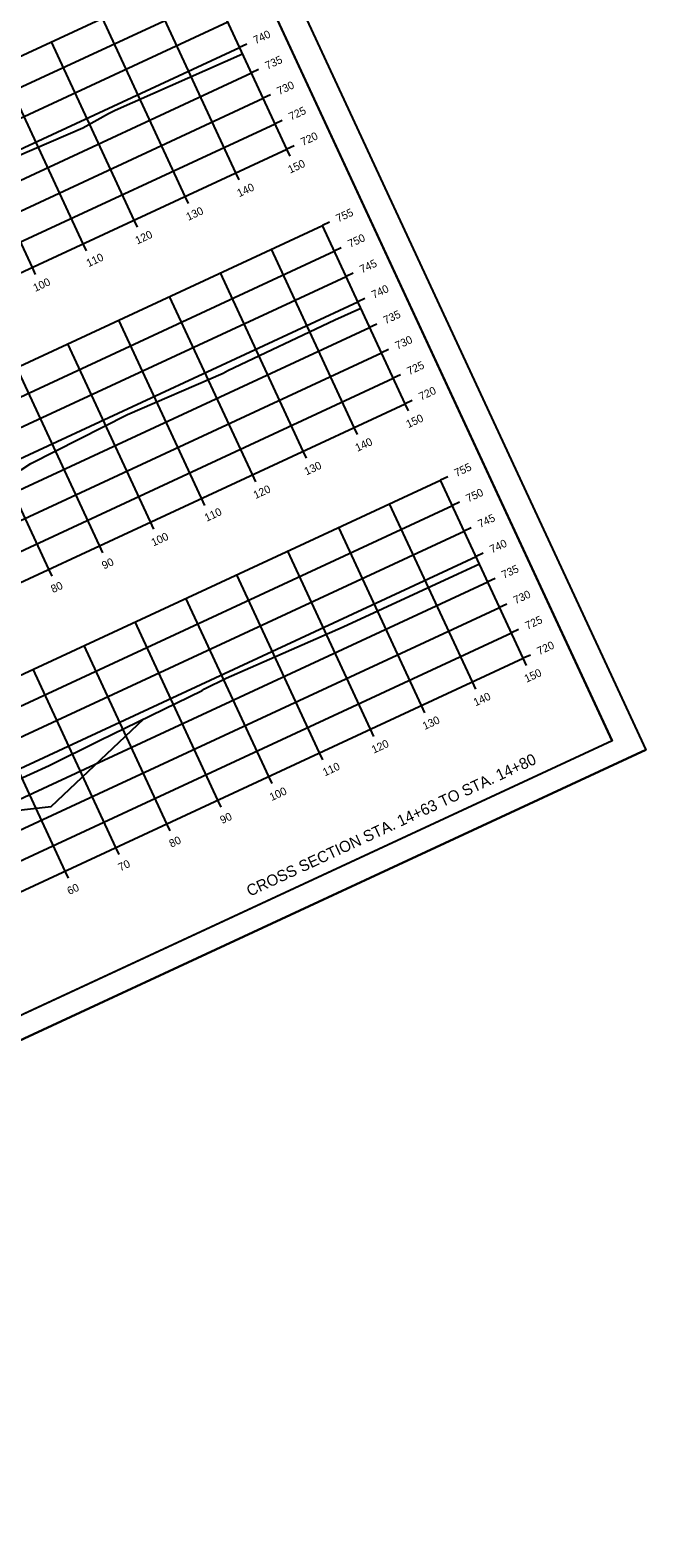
# Model space of a CAD drawing. Extents: x 1354696 to 1366163, y 660729 to 670380.
# Drawn here: x 1359055.3 to 1359165, y 665712.2 to 665980.8 of the extents above; entities that cross this region are included whole.
import ezdxf

# ---------------------------------------------------------------- set-up
doc = ezdxf.new("R2010")
doc.units = 0
for name, color, linetype in [('R_Axis', 7, 'Continuous'), ('R_Axis Annot', 7, 'Continuous'), ('R_Border', 7, 'Continuous'), ('R_Draft', 7, 'Continuous'), ('R_Exist Surface', 7, 'Continuous'), ('R_Fin Surface', 7, 'Continuous'), ('R_Grid', 7, 'Continuous'), ('R_No Plot', 7, 'Continuous')]:
    doc.layers.add(name, color=color, linetype=linetype)

msp = doc.modelspace()

# ---------------------------------------------------------------- linework, layer by layer
at = {"layer": 'R_Axis'}
for p, q in [((1359101.06, 665959.57), (1359086.32, 665991.32)), ((1359093.91, 665978.3), (1359092.64, 665977.71)), ((1359096.02, 665973.77), (1359094.75, 665973.18)), ((1359098.12, 665969.23), (1359096.85, 665968.64)), ((1359100.23, 665964.7), (1359098.96, 665964.11)), ((1358828.96, 665833.24), (1359101.06, 665959.57)), ((1359102.33, 665960.16), (1359101.06, 665959.57)), ((1359101.65, 665958.3), (1359101.06, 665959.57)), ((1359092.58, 665954.09), (1359091.99, 665955.36)), ((1359083.51, 665949.88), (1359082.92, 665951.15)), ((1359074.44, 665945.67), (1359073.85, 665946.94)), ((1359108.65, 665946.56), (1359107.38, 665945.97)), ((1359122.12, 665914.22), (1359107.38, 665945.97)), ((1359065.37, 665941.46), (1359064.78, 665942.73)), ((1359110.75, 665942.02), (1359109.48, 665941.43)), ((1359056.3, 665937.25), (1359055.71, 665938.52)), ((1359112.86, 665937.49), (1359111.59, 665936.9)), ((1359114.97, 665932.95), (1359113.7, 665932.36)), ((1359117.07, 665928.42), (1359115.8, 665927.83)), ((1359119.18, 665923.88), (1359117.91, 665923.29)), ((1359121.28, 665919.35), (1359120.01, 665918.76)), ((1358850.01, 665787.89), (1359122.12, 665914.22)), ((1359123.39, 665914.81), (1359122.12, 665914.22)), ((1359122.71, 665912.95), (1359122.12, 665914.22)), ((1359113.64, 665908.74), (1359113.05, 665910.01)), ((1359104.57, 665904.53), (1359103.98, 665905.8)), ((1359095.5, 665900.32), (1359094.91, 665901.59)), ((1359129.7, 665901.21), (1359128.43, 665900.62)), ((1359143.17, 665868.87), (1359128.43, 665900.62)), ((1359086.43, 665896.11), (1359085.84, 665897.38)), ((1359131.81, 665896.67), (1359130.54, 665896.08)), ((1359077.36, 665891.9), (1359076.77, 665893.17)), ((1359133.91, 665892.14), (1359132.65, 665891.55)), ((1359068.29, 665887.69), (1359067.7, 665888.96)), ((1359136.02, 665887.6), (1359134.75, 665887.01)), ((1359059.22, 665883.48), (1359058.63, 665884.75)), ((1359138.13, 665883.07), (1359136.86, 665882.48)), ((1359140.23, 665878.53), (1359138.96, 665877.94)), ((1359142.34, 665874), (1359141.07, 665873.41)), ((1358871.07, 665742.54), (1359143.17, 665868.87)), ((1359144.44, 665869.46), (1359143.17, 665868.87)), ((1359143.76, 665867.6), (1359143.17, 665868.87)), ((1359134.69, 665863.39), (1359134.1, 665864.66)), ((1359125.62, 665859.18), (1359125.03, 665860.45)), ((1359116.55, 665854.97), (1359115.96, 665856.24)), ((1359107.48, 665850.76), (1359106.89, 665852.03)), ((1359098.41, 665846.55), (1359097.82, 665847.82)), ((1359089.34, 665842.34), (1359088.75, 665843.61)), ((1359080.27, 665838.13), (1359079.68, 665839.4)), ((1359071.2, 665833.91), (1359070.61, 665835.18)), ((1359062.13, 665829.7), (1359061.54, 665830.97))]:
    msp.add_line(p, q, dxfattribs=at)
at = {"layer": 'R_Border'}
for q in [(1359072.49, 666040.53), (1358872.23, 665721.03)]:
    msp.add_line((1359159.01, 665854.18), q, dxfattribs=at)
at = {"layer": 'R_Exist Surface'}
for points in [[(1359052.99, 665958.3), (1359064.71, 665963.37), (1359069.26, 665965.94), (1359070.45, 665966.51), (1359093.17, 665976.58)], [(1359053.71, 665902.42), (1359055.46, 665903.6), (1359072.65, 665912.31), (1359089.69, 665919.67), (1359090.54, 665920.16), (1359109.57, 665929.16), (1359114.23, 665931.22)], [(1359052.19, 665846.79), (1359055.33, 665848.21), (1359058.69, 665849.76), (1359067.68, 665854.26), (1359085.98, 665863.15), (1359086.37, 665863.41), (1359090.21, 665865.35), (1359094.6, 665867.25), (1359111.11, 665874.49), (1359131.53, 665883.93), (1359135.35, 665885.72)]]:
    msp.add_lwpolyline(points, dxfattribs=at)
at = {"layer": 'R_Fin Surface'}
msp.add_lwpolyline([(1358936.65, 665790.65), (1358947.7, 665791.9), (1358971.24, 665814.12), (1358974.3, 665816.16), (1358981.35, 665820.85), (1358986.74, 665823.49), (1358996.62, 665828.32), (1359006.69, 665832.75), (1359012.24, 665835.06), (1359019.88, 665837.33), (1359023.86, 665838.51), (1359059.06, 665842.5), (1359075.59, 665858.1)], dxfattribs=at)
at = {"layer": 'R_Grid'}
for p, q in [((1358814.22, 665864.99), (1359086.32, 665991.32)), ((1359101.06, 665959.57), (1359086.32, 665991.32)), ((1358816.33, 665860.45), (1359088.43, 665986.78)), ((1359091.99, 665955.36), (1359077.25, 665987.11)), ((1358818.43, 665855.92), (1359090.53, 665982.25)), ((1359082.92, 665951.15), (1359068.18, 665982.9)), ((1359073.85, 665946.94), (1359059.11, 665978.69)), ((1358820.54, 665851.38), (1359092.64, 665977.71)), ((1358822.64, 665846.85), (1359094.75, 665973.18)), ((1359064.78, 665942.73), (1359050.04, 665974.48)), ((1359055.71, 665938.52), (1359040.97, 665970.26)), ((1358824.75, 665842.31), (1359096.85, 665968.64)), ((1358826.85, 665837.78), (1359098.96, 665964.11)), ((1358828.96, 665833.24), (1359101.06, 665959.57)), ((1358835.27, 665819.64), (1359107.38, 665945.97)), ((1359122.12, 665914.22), (1359107.38, 665945.97)), ((1358837.38, 665815.1), (1359109.48, 665941.43)), ((1359113.05, 665910.01), (1359098.31, 665941.76)), ((1358839.49, 665810.57), (1359111.59, 665936.9)), ((1359103.98, 665905.8), (1359089.24, 665937.55)), ((1359094.91, 665901.59), (1359080.17, 665933.34)), ((1358841.59, 665806.03), (1359113.7, 665932.36)), ((1358843.7, 665801.5), (1359115.8, 665927.83)), ((1359085.84, 665897.38), (1359071.1, 665929.12)), ((1359076.77, 665893.17), (1359062.03, 665924.91)), ((1358845.8, 665796.96), (1359117.91, 665923.29)), ((1359067.7, 665888.96), (1359052.96, 665920.7)), ((1358847.91, 665792.43), (1359120.01, 665918.76)), ((1359058.63, 665884.75), (1359043.89, 665916.49)), ((1358850.01, 665787.89), (1359122.12, 665914.22)), ((1358856.33, 665774.29), (1359128.43, 665900.62)), ((1359143.17, 665868.87), (1359128.43, 665900.62)), ((1358858.44, 665769.75), (1359130.54, 665896.08)), ((1359134.1, 665864.66), (1359119.36, 665896.41)), ((1358860.54, 665765.22), (1359132.65, 665891.55)), ((1359125.03, 665860.45), (1359110.29, 665892.2)), ((1358862.65, 665760.68), (1359134.75, 665887.01)), ((1359115.96, 665856.24), (1359101.22, 665887.98)), ((1358864.75, 665756.15), (1359136.86, 665882.48)), ((1359106.89, 665852.03), (1359092.15, 665883.77)), ((1359097.82, 665847.82), (1359083.08, 665879.56)), ((1358866.86, 665751.61), (1359138.96, 665877.94)), ((1359088.75, 665843.61), (1359074.01, 665875.35)), ((1358868.96, 665747.08), (1359141.07, 665873.41)), ((1359079.68, 665839.4), (1359064.94, 665871.14)), ((1358871.07, 665742.54), (1359143.17, 665868.87)), ((1359070.61, 665835.18), (1359055.87, 665866.93)), ((1359061.54, 665830.97), (1359046.8, 665862.72))]:
    msp.add_line(p, q, dxfattribs=at)
at = {"layer": 'R_No Plot'}
msp.add_line((1358862.66, 665712.2), (1359165, 665852.57), dxfattribs=at)
for points in [[(1358772.82, 665905.7), (1359075.16, 666046.07), (1359165, 665852.57), (1358862.66, 665712.2)], [(1358997.88, 666005.89), (1359015.68, 666014.15), (1359019.84, 666005.19), (1359034.45, 666011.98), (1359055.5, 666021.75), (1359067.46, 665996.26), (1359088.51, 666006.03), (1359159.01, 665854.18), (1358872.23, 665721.03), (1358785.71, 665907.39)]]:
    msp.add_lwpolyline(points, close=True, dxfattribs=at)

# ---------------------------------------------------------------- texts
at = {"layer": 'R_Axis Annot'}
for s, p in [('740', (1359095.47, 665978.26)), ('735', (1359097.58, 665973.72)), ('730', (1359099.69, 665969.19)), ('725', (1359101.79, 665964.65)), ('720', (1359103.9, 665960.12)), ('150', (1359101.64, 665955.21)), ('140', (1359092.57, 665951)), ('130', (1359083.5, 665946.79)), ('755', (1359110.21, 665946.51)), ('120', (1359074.43, 665942.58)), ('750', (1359112.32, 665941.98)), ('110', (1359065.72, 665938.53)), ('745', (1359114.42, 665937.44)), ('100', (1359056.24, 665934.13)), ('740', (1359116.53, 665932.91)), ('735', (1359118.64, 665928.37)), ('730', (1359120.74, 665923.84)), ('725', (1359122.85, 665919.3)), ('720', (1359124.95, 665914.77)), ('150', (1359122.69, 665909.86)), ('140', (1359113.62, 665905.65)), ('130', (1359104.55, 665901.44)), ('755', (1359131.27, 665901.16)), ('120', (1359095.48, 665897.23)), ('750', (1359133.37, 665896.63)), ('110', (1359086.77, 665893.18)), ('745', (1359135.48, 665892.09)), ('100', (1359077.29, 665888.78)), ('740', (1359137.58, 665887.56)), ('90', (1359068.48, 665884.69)), ('735', (1359139.69, 665883.02)), ('80', (1359059.41, 665880.48)), ('730', (1359141.8, 665878.49)), ('725', (1359143.9, 665873.95)), ('720', (1359146.01, 665869.42)), ('150', (1359143.75, 665864.51)), ('140', (1359134.68, 665860.3)), ('130', (1359125.61, 665856.09)), ('120', (1359116.54, 665851.88)), ('110', (1359107.83, 665847.83)), ('100', (1359098.35, 665843.43)), ('90', (1359089.54, 665839.34)), ('80', (1359080.47, 665835.13)), ('70', (1359071.4, 665830.92)), ('60', (1359062.3, 665826.69))]:
    msp.add_text(s, height=1.4, rotation=24.9042, dxfattribs=at).set_placement(p)
at = {"layer": 'R_Draft'}
msp.add_text('CROSS SECTION STA. 14+63 TO STA. 14+80', height=2, rotation=24.9042, dxfattribs=at).set_placement((1359094.45, 665826.4))

doc.saveas('drawing.dxf')
